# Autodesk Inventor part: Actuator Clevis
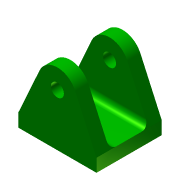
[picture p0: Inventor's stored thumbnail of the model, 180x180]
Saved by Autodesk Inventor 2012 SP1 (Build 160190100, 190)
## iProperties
Created: 2012-04
Part Number: Actuator Clevis
Material: Steel, Mild
Document SubType Name: Modeling
Designer: dmm70056
Mass: 129.061 g
Surface Area: 65.9908 cm^2
Volume: 16.4199 cm^3
Density: 7.86 g/cm^3
Author: dmm70056
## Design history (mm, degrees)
sketch "Sketch1"
  geometry: L1 (0, 0)-(38.1, 0); L2 (38.1, 0)-(38.1, 6.35); L3 (38.1, 6.35)-(27.731, 29.319); L4 (10.369, 29.319)-(0, 6.35); L5 (0, 6.35)-(0, 0); A1 r 9.525 centre (19.05, 25.4) between (27.731, 29.319) and (10.369, 29.319)
  constraints: 10 end point, 2 perpendicular, 2 point on circle, 2 tangent, 1 centre point, 1 horizontal, 1 horizontal alignment
  dimensions: "d0" = 6.35 distance of L4.end L1.start; "d1" = 38.1 distance of L1.start L1.end; "d2" = 19.05 distance from line of L5 A1.centre (= 0.5 x d1); "d3" = 25.4 distance from line of L1 A1.centre; "d4" = 9.525 radius of A1
extrude "Extrusion1" new body sketch "Sketch1" stored distance "d5" = 31.75; taper "d6" = 0 deg
sketch "Sketch2"
  geometry: L1 (-31.75, 34.925)-(0, 34.925) reference; L2 (-31.75, 6.35)-(0, 6.35) reference; L3 (-6.35, 34.925)-(-25.4, 34.925); L4 (-25.4, 34.925)-(-25.4, 6.35); L5 (-25.4, 6.35)-(-6.35, 6.35); L6 (-6.35, 6.35)-(-6.35, 34.925); L7 (0, 34.925)-(0, 29.319) reference; L8 (-31.75, 29.319)-(-31.75, 6.35) reference; 1 further point
  constraints: 8 end point, 2 parallel, 2 point on line, 1 horizontal, 1 perpendicular
  dimensions: "d7" = 6.35 distance between parallel lines of L7 L6; "d8" = 6.35 distance between parallel lines of L8 L4
extrude "Extrusion2" cut sketch "Sketch2" stored distance "d9" = 31.75; taper "d10" = 0 deg
fillet "Fillet1" dims "d11" = 3.175
hole "Hole1" diameter "d14" = 6.35; stored, may be unused: countersink angle "d18" = 82 deg, drill point angle "d20" = 118 deg; dims "d12" = 25.4, "d13" = 25.4, "d15" = 19.05, "d16" = 9.525, "d17" = 6.35, "d19" = 25.4
body "Solid1"
